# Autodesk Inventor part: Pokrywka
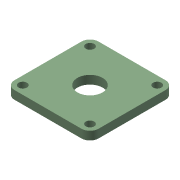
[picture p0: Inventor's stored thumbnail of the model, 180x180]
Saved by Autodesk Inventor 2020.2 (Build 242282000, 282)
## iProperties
Created: 2005-10
Part Number: Pokrywka
Document SubType Name: Modeling
Designer: F.Stasiak
Density: 1 g/cm^3
Material: Ogólny
Appearance: Zielony pastelowy
Manager: www.cadconsulting.pl
Company: Fabian Stasiak CAD Consulting
Author: F.Stasiak
Subject: Zbiór ćwiczeń. Autodesk Inventor 2020. Kurs podstawowy
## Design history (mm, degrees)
sketch "Szkic1"
  geometry: L1 (0, 40)-(0, -40) reference; L2 (-10, 50)-(-90, 50) reference; L3 (-100, 40)-(-100, -40) reference; L4 (-90, -50)-(-10, -50) reference; C1 r 37.5 at (-50.839, -0.839) reference; C2 r 4 at (-90, -40) reference; C3 r 4 at (-10, 40) reference; C4 r 4 at (-10, -40) reference; C5 r 4 at (-90, 40) reference; A1 r 10 centre (-10, -40) between (-10, -50) and (0, -40) reference; A2 r 10 centre (-10, 40) between (0, 40) and (-10, 50) reference; A3 r 10 centre (-90, 40) between (-90, 50) and (-100, 40) reference; A4 r 10 centre (-90, -40) between (-100, -40) and (-90, -50) reference
  node "Odniesienie1"
extrude "Wyciągnięcie proste1" new body sketch "Szkic1" distance "d0" = 10; taper "d1" = 0 deg
hole "Otwór2" sketch "Szkic1" diameter "d12" = 10; stored, may be unused: countersink angle "d16" = 90 deg, drill point angle "d18" = 118 deg; dims "d13" = 6, "d14" = 4, "d15" = 2, "d17" = 8
sketch "Szkic3"
  geometry: L1 (-10, 40)-(-90, -40); C1 r 5 at (-10, 40) reference; C2 r 5 at (-90, -40) reference; C3 r 15 at (-50, 0)
  constraints: 2 end point, 1 centre point, 1 midpoint
  dimensions: "d19" = 30 diameter of C3
extrude "Wyciągnięcie proste3" cut sketch "Szkic3" extent not by distance; stored distance "d20" = 5; taper "d21" = 0 deg
node "Bryła1"
node "Korpusy bryłowe"
node "Korpusy powierzchniowe"
